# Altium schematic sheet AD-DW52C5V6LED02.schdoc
size 127 x 101 mm
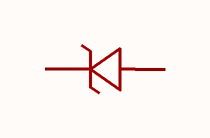
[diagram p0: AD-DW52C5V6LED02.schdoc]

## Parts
D?  ad-dw52c5v6led02  [WBFBP-02C_L1.0-W0.6-RD]  (value not drawn)

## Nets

Not connected (* = marked no-connect by the designer): D? 1(A) 2(C)

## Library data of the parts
D? = ad-dw52c5v6led02: 二极管配置:1个独立式;稳压值(标称值):5.6V;稳压值(范围值):5.2V~6V;耗散功率(Pd):100mW;; Manufacturer: CJ(江苏长电/长晶); AddInBom: yes; Diode Configuration: 1个独立式; Zener Voltage(Nom): 5.6V; Reverse Leakage Current (Ir): 1uA@2V; Pd - Power Dissipation: 100mW; Impedance(Zzt): 40Ω; Impedance(Zzk): 400Ω; Operating Junction Temperature Range: -55℃~+150℃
